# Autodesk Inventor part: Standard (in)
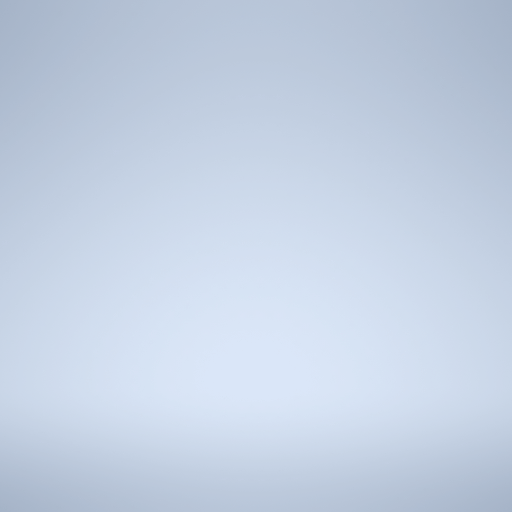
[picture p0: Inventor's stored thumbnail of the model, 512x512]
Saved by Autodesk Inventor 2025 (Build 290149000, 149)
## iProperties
Shininess: 64.0
Length Units: 11272
Angle Units: 11279
Time Units: 11290
Mass Units: 11286
Length Display Precision: 3
Angle Display Precision: 2
Compacted: True
Part Number: Standard (in)
Document SubType Name: Modeling
Created: 2002-08
Density: 1 g/cm^3
Material: Generico
Appearance: Default
Density: 0.0
Volumn: 0.0
Area: 0.0
PropertySet Name: Model Information
Control State: 0
Master: False
Checked Out: False
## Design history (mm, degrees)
